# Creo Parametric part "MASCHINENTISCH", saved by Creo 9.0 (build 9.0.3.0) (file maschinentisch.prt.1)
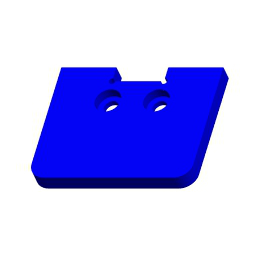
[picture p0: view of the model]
Units: millimeter Kilogram Sec (mmKs); MM, KILOGRAM, SECS
Materials in the file: STAHL

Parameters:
  SCHRAUBEN_GROESSE = "M4x.7"
  METRISCH = "JA"
  WERKSTOFF = "Stahl"
  ERSTELLER = "ARINDA"
  BENENNUNG = "XXX"
  TEILETYP = "K"
  PTC_MASTER_MATERIAL = "STAHL"

Other parameters: ANSENKDURCHMESSER, ANSENKTIEFE, BOHR_DURCHM, MASSE

Created from: ARINDA_STARTTEIL.PRT

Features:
  1. coordinate system
  2. datum plane "RECHTS_Y-Z"
  3. datum plane "OBEN_X-Z"
  4. datum plane "VORNE_X-Y"
  5. datum axis
  6. datum axis
  7. datum axis
  8. datum point "PNT0"
  9. extrusion "Profil 1"
  10. extruded cut "Profil 2"
  11. extruded cut "Profil 3"
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
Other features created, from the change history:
  coordinate system "CS1"
  sketch "Skizze 1"
  hole "Bohrung 1"
  pattern "Muster 1"
  hole "Bohrung 1 [8]"
  round "Rundung 1"

Other named items: MASCHINENTISCH, NUT, FREIMACHUNG, BEFESTIGUNG, A_X, A_Y, A_Z, CS0

Layers: 01_ACHSEN, 01_ACHSEN_STD, 01_EBENEN_STD, 01_KOORDSYS_STD, 01_KURVEN, 01_PUNKTE_STD, VOLUMENGEOMETRIE

Notes: M4x.7 | LÖSCHEN |  BOHREN (  | 4.500 | DURCH |   -(  |  ) BOHRUNG

Surfaces: 11 plane, 10 cylinder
